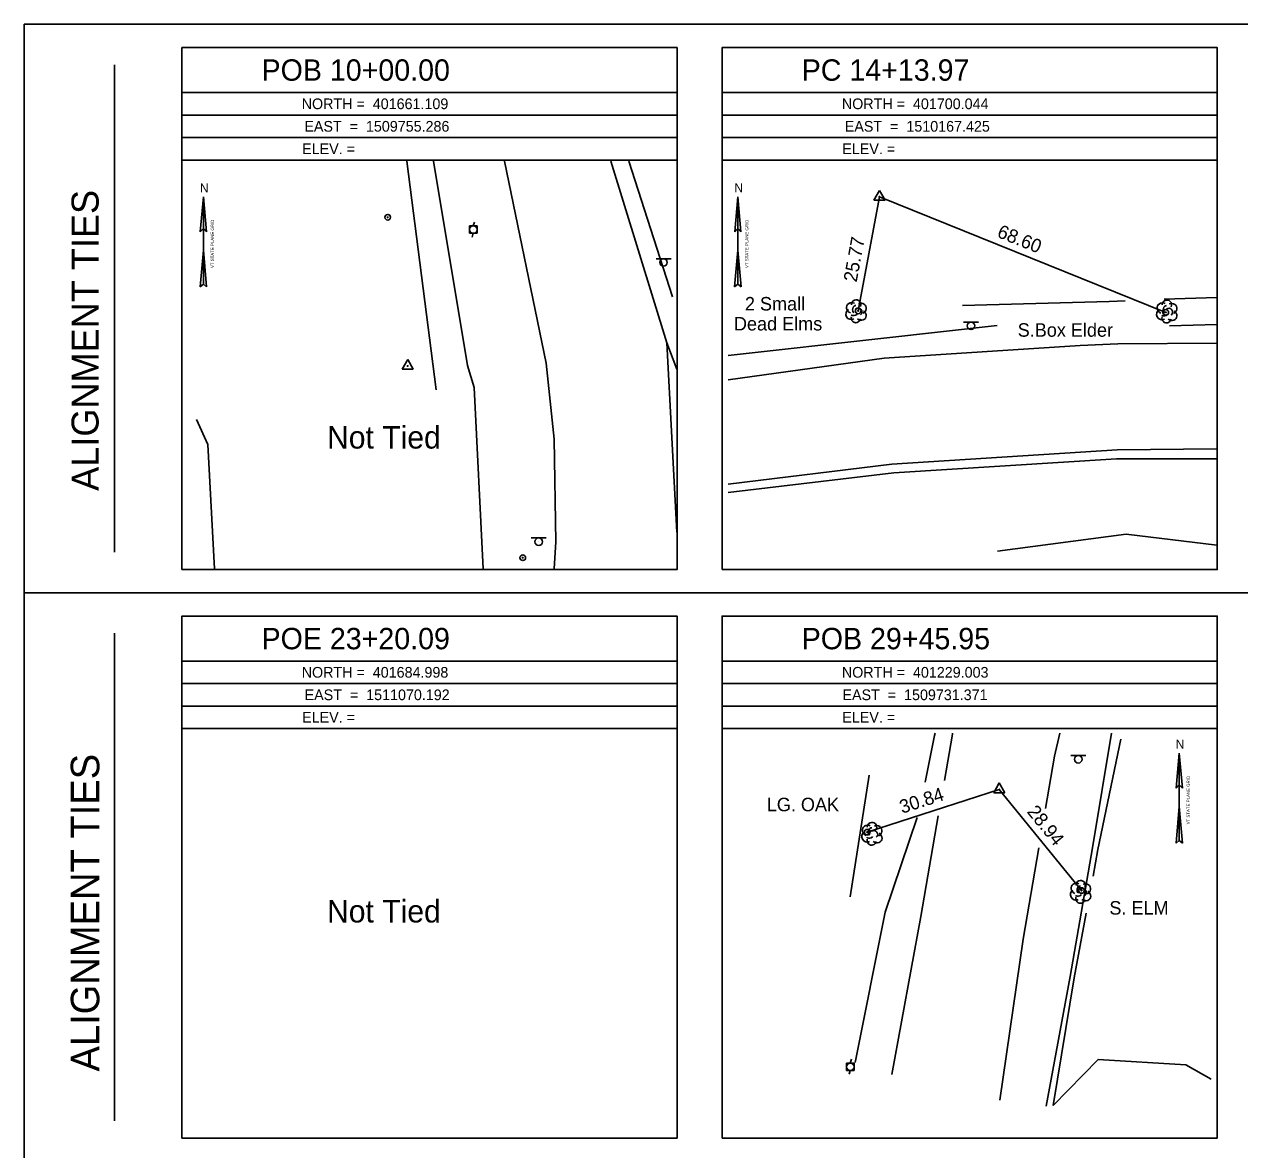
# Model space of a CAD drawing. Extents: x 1508412 to 1509054, y 401108 to 401963.
# Drawn here: x 1508411.9 to 1508681.9, y 401277.6 to 401527.7 of the extents above; entities that cross this region are included whole.
import ezdxf

# ---------------------------------------------------------------- set-up
doc = ezdxf.new("R2010")
doc.units = 0
for name, color, linetype in [('CBP', 7, 'Continuous'), ('CPH', 7, 'Continuous'), ('Default', 7, 'Continuous'), ('L_C', 7, 'Continuous'), ('LAWA', 7, 'Continuous'), ('LAWE', 7, 'Continuous'), ('Level 5', 7, 'Continuous'), ('LFNC', 7, 'Continuous'), ('LTD', 7, 'Continuous'), ('LWS', 7, 'Continuous'), ('NBL1', 7, 'Continuous'), ('NBL2', 7, 'Continuous'), ('NNA_P', 7, 'Continuous'), ('PET', 7, 'Continuous'), ('RGR', 7, 'Continuous'), ('SSGN', 7, 'Continuous'), ('UP', 7, 'Continuous'), ('UPGW', 7, 'Continuous')]:
    doc.layers.add(name, color=color, linetype=linetype)

msp = doc.modelspace()

# ---------------------------------------------------------------- linework, layer by layer
at = {"layer": 'CBP'}
for centre, radius in [((1508597.17, 401464.03), 0.625), ((1508597.17, 401464.03), 0.0833), ((1508665.49, 401463.7), 0.625), ((1508665.49, 401463.7), 0.0833), ((1508599.16, 401348.2), 0.625), ((1508599.16, 401348.2), 0.0833), ((1508646.76, 401335.23), 0.625), ((1508646.76, 401335.23), 0.0833)]:
    msp.add_circle(centre, radius, dxfattribs=at)
at = {"layer": 'CPH'}
for p, q in [((1508600.62, 401488.65), (1508601.87, 401490.82)), ((1508603.12, 401488.65), (1508601.87, 401490.82)), ((1508600.62, 401488.65), (1508603.12, 401488.65)), ((1508601.87, 401489.37), (1508601.87, 401489.37)), ((1508495.83, 401451.08), (1508497.08, 401453.24)), ((1508498.33, 401451.08), (1508497.08, 401453.24)), ((1508497.08, 401451.8), (1508497.08, 401451.8)), ((1508495.83, 401451.08), (1508498.33, 401451.08)), ((1508627.26, 401356.97), (1508628.51, 401359.13)), ((1508629.76, 401356.97), (1508628.51, 401359.13)), ((1508628.51, 401357.69), (1508628.51, 401357.69)), ((1508627.26, 401356.97), (1508629.76, 401356.97))]:
    msp.add_line(p, q, dxfattribs=at)
for centre in [(1508601.87, 401489.37), (1508497.08, 401451.8), (1508628.51, 401357.69)]:
    msp.add_circle(centre, 0.0833, dxfattribs=at)
at = {"layer": 'Default'}
for p, q in [((1508597.17, 401464.03), (1508601.87, 401489.37)), ((1508601.87, 401489.37), (1508665.49, 401463.7)), ((1508599.16, 401348.2), (1508628.51, 401357.69)), ((1508628.51, 401357.69), (1508646.76, 401335.23))]:
    msp.add_line(p, q, dxfattribs=at)
at = {"layer": 'LAWA'}
for points in [[(1508496.9, 401497.27), (1508503.43, 401446.52)], [(1508454.15, 401406.72), (1508452.66, 401434.32), (1508450.15, 401439.87)], [(1508612.05, 401359.27), (1508614.08, 401369.67), (1508614.23, 401370.23)], [(1508649.32, 401338.41), (1508650.42, 401344.34), (1508655.52, 401368.88)], [(1508596.45, 401297), (1508603.17, 401330.41), (1508610.27, 401351.45)], [(1508640.44, 401287.44), (1508645.11, 401315.79), (1508647.79, 401330.17)], [(1508640.44, 401287.44), (1508650.43, 401297.69), (1508669.92, 401296.5), (1508675.55, 401293.29)]]:
    msp.add_lwpolyline(points, dxfattribs=at)
at = {"layer": 'LAWE'}
msp.add_lwpolyline([(1508628.14, 401410.67), (1508656.72, 401414.43), (1508676.83, 401411.94)], dxfattribs=at)
at = {"layer": 'LFNC'}
for points in [[(1508666.32, 401460.73), (1508676.83, 401460.99)], [(1508638.88, 401287.32), (1508644.23, 401316.1), (1508649.21, 401344.75), (1508653.46, 401370.23)], [(1508595.35, 401333.79), (1508599.56, 401360.88)]]:
    msp.add_lwpolyline(points, dxfattribs=at)
at = {"layer": 'LTD'}
for p, q in [((1508596.66, 401464), (1508596.66, 401464)), ((1508596.66, 401464), (1508596.66, 401464)), ((1508665.67, 401463.95), (1508665.67, 401463.95)), ((1508665.67, 401463.95), (1508665.67, 401463.95)), ((1508600.17, 401347.89), (1508600.17, 401347.89)), ((1508600.17, 401347.89), (1508600.17, 401347.89)), ((1508646.53, 401334.99), (1508646.53, 401334.99)), ((1508646.53, 401334.99), (1508646.53, 401334.99))]:
    msp.add_line(p, q, dxfattribs=at)
for centre in [(1508596.71, 401465.43), (1508665.72, 401465.39), (1508600.22, 401349.32), (1508646.57, 401336.42)]:
    msp.add_arc(centre, 1.05, 335.5272, 180.9563, dxfattribs=at)
for centre, major_axis, ratio, start_param, end_param in [((1508595.87, 401464.66), (1.21, -0.51), 0.895232, 1.570796, 4.712389), ((1508596.46, 401464.46), (-0.208, -0.792), 0.645439, 3.141593, 6.283185), ((1508597.71, 401464.58), (-1.14, -0.48), 0.949671, 1.570796, 4.712389), ((1508664.88, 401464.62), (1.21, -0.51), 0.895232, 1.570796, 4.712389), ((1508665.46, 401464.41), (-0.208, -0.792), 0.645439, 3.141593, 6.283185), ((1508666.71, 401464.53), (-1.14, -0.48), 0.949671, 1.570796, 4.712389), ((1508595.58, 401463.29), (0.58, -1.04), 0.959034, 3.141593, 6.283185), ((1508596.66, 401462.5), (0.26, 1.06), 0.942809, 1.570796, 4.712389), ((1508596.21, 401463.25), (-0.625, -0.083), 0.423636, 0, 3.141593), ((1508597.16, 401463.83), (-0.5, 0.667), 0.989748, 3.141593, 6.283185), ((1508597.66, 401463.16), (-1.09, 0.79), 0.841452, 1.570796, 4.712389), ((1508664.59, 401463.24), (0.58, -1.04), 0.959034, 3.141593, 6.283185), ((1508665.67, 401462.45), (0.26, 1.06), 0.942809, 1.570796, 4.712389), ((1508665.21, 401463.2), (-0.625, -0.083), 0.423636, 0, 3.141593), ((1508666.17, 401463.78), (-0.5, 0.667), 0.989748, 3.141593, 6.283185), ((1508666.67, 401463.12), (-1.09, 0.79), 0.841452, 1.570796, 4.712389), ((1508599.38, 401348.55), (1.21, -0.51), 0.895232, 1.570796, 4.712389), ((1508599.96, 401348.35), (-0.208, -0.792), 0.645439, 3.141593, 6.283185), ((1508601.21, 401348.47), (-1.14, -0.48), 0.949671, 1.570796, 4.712389), ((1508599.09, 401347.18), (0.58, -1.04), 0.959034, 3.141593, 6.283185), ((1508600.17, 401346.39), (0.26, 1.06), 0.942809, 1.570796, 4.712389), ((1508599.71, 401347.14), (-0.625, -0.083), 0.423636, 0, 3.141593), ((1508600.67, 401347.72), (-0.5, 0.667), 0.989748, 3.141593, 6.283185), ((1508601.17, 401347.05), (-1.09, 0.79), 0.841452, 1.570796, 4.712389), ((1508645.74, 401335.66), (1.21, -0.51), 0.895232, 1.570796, 4.712389), ((1508646.32, 401335.45), (-0.208, -0.792), 0.645439, 3.141593, 6.283185), ((1508647.03, 401334.82), (-0.5, 0.667), 0.989748, 3.141593, 6.283185), ((1508647.57, 401335.57), (-1.14, -0.48), 0.949671, 1.570796, 4.712389), ((1508645.44, 401334.28), (0.58, -1.04), 0.959034, 3.141593, 6.283185), ((1508646.53, 401333.49), (0.26, 1.06), 0.942809, 1.570796, 4.712389), ((1508646.07, 401334.24), (-0.625, -0.083), 0.423636, 0, 3.141593), ((1508647.53, 401334.16), (-1.09, 0.79), 0.841452, 1.570796, 4.712389)]:
    msp.add_ellipse(centre, major_axis=major_axis, ratio=ratio, start_param=start_param, end_param=end_param, dxfattribs=at)
at = {"layer": 'LWS'}
for points in [[(1508502.79, 401497.27), (1508510.35, 401451.87), (1508511.84, 401447.03), (1508513.86, 401406.72)], [(1508656.44, 401466.27), (1508652.94, 401466.09), (1508620.31, 401465.21)], [(1508676.83, 401466.98), (1508665.13, 401466.61)]]:
    msp.add_lwpolyline(points, dxfattribs=at)
at = {"layer": 'NBL1'}
msp.add_lwpolyline([(1508411.91, 401107.72), (1509051.91, 401107.72), (1509051.91, 401527.72), (1508411.91, 401527.72)], close=True, dxfattribs=at)
at = {"layer": 'NBL2'}
for p, q in [((1508431.91, 401410.38), (1508431.91, 401518.72)), ((1508556.91, 401512.55), (1508446.91, 401512.55)), ((1508676.91, 401512.55), (1508566.91, 401512.55)), ((1508556.91, 401507.55), (1508446.91, 401507.55)), ((1508676.91, 401507.55), (1508566.91, 401507.55)), ((1508556.91, 401502.55), (1508446.91, 401502.55)), ((1508676.91, 401502.55), (1508566.91, 401502.55)), ((1508556.91, 401497.55), (1508446.91, 401497.55)), ((1508676.91, 401497.55), (1508566.91, 401497.55)), ((1508411.91, 401401.38), (1509051.91, 401401.38)), ((1508431.91, 401284.05), (1508431.91, 401392.38)), ((1508556.91, 401386.22), (1508446.91, 401386.22)), ((1508676.91, 401386.22), (1508566.91, 401386.22)), ((1508556.91, 401381.22), (1508446.91, 401381.22)), ((1508676.91, 401381.22), (1508566.91, 401381.22)), ((1508556.91, 401376.22), (1508446.91, 401376.22)), ((1508676.91, 401376.22), (1508566.91, 401376.22)), ((1508556.91, 401371.22), (1508446.91, 401371.22)), ((1508676.91, 401371.22), (1508566.91, 401371.22))]:
    msp.add_line(p, q, dxfattribs=at)
for points in [[(1508446.91, 401406.55), (1508556.91, 401406.55), (1508556.91, 401522.55), (1508446.91, 401522.55)], [(1508566.91, 401406.55), (1508676.91, 401406.55), (1508676.91, 401522.55), (1508566.91, 401522.55)], [(1508446.91, 401280.22), (1508556.91, 401280.22), (1508556.91, 401396.22), (1508446.91, 401396.22)], [(1508566.91, 401280.22), (1508676.91, 401280.22), (1508676.91, 401396.22), (1508566.91, 401396.22)]]:
    msp.add_lwpolyline(points, close=True, dxfattribs=at)
at = {"layer": 'NNA_P'}
for p, q in [((1508450.99, 401481.58), (1508451.69, 401489.37)), ((1508451.69, 401469.99), (1508451.69, 401489.37)), ((1508452.38, 401481.58), (1508451.69, 401489.37)), ((1508569.73, 401481.58), (1508570.43, 401489.37)), ((1508570.43, 401469.99), (1508570.43, 401489.37)), ((1508571.12, 401481.58), (1508570.43, 401489.37)), ((1508450.99, 401481.58), (1508451.69, 401482.34)), ((1508452.38, 401481.58), (1508451.69, 401482.34)), ((1508569.73, 401481.58), (1508570.43, 401482.34)), ((1508571.12, 401481.58), (1508570.43, 401482.34)), ((1508451.69, 401477.52), (1508450.97, 401469.35)), ((1508451.69, 401477.52), (1508452.41, 401469.35)), ((1508570.43, 401477.52), (1508569.71, 401469.35)), ((1508570.43, 401477.52), (1508571.15, 401469.35)), ((1508451.69, 401469.99), (1508450.97, 401469.35)), ((1508451.69, 401469.99), (1508452.41, 401469.35)), ((1508570.43, 401469.99), (1508569.71, 401469.35)), ((1508570.43, 401469.99), (1508571.15, 401469.35)), ((1508667.78, 401357.96), (1508668.47, 401365.75)), ((1508668.48, 401346.37), (1508668.47, 401365.75)), ((1508669.17, 401357.96), (1508668.47, 401365.75)), ((1508667.78, 401357.96), (1508668.47, 401358.72)), ((1508669.17, 401357.96), (1508668.47, 401358.72)), ((1508668.48, 401353.9), (1508667.76, 401345.73)), ((1508668.47, 401353.9), (1508669.2, 401345.73)), ((1508668.48, 401346.37), (1508667.76, 401345.73)), ((1508668.48, 401346.37), (1508669.2, 401345.73))]:
    msp.add_line(p, q, dxfattribs=at)
at = {"layer": 'PET'}
for points in [[(1508518.59, 401497.27), (1508527.84, 401452.39), (1508529.59, 401435.54), (1508529.95, 401412.68), (1508529.59, 401406.72)], [(1508542.24, 401497.27), (1508554.62, 401456.93)], [(1508554.62, 401456.93), (1508556.87, 401451.08)], [(1508554.62, 401456.93), (1508556.87, 401414.86)], [(1508568.3, 401448.68), (1508602.96, 401453.53), (1508646.5, 401456.32), (1508654.83, 401456.68), (1508676.83, 401456.87)], [(1508568.3, 401425.55), (1508604.63, 401429.98), (1508654.68, 401433.18), (1508676.83, 401433.38)], [(1508616.3, 401359.7), (1508618.07, 401369.97)], [(1508618.07, 401369.97), (1508618.11, 401370.23)], [(1508640.75, 401365.09), (1508641.98, 401370.23)], [(1508638.76, 401353.42), (1508640.75, 401365.09)], [(1508604.61, 401294.35), (1508611.1, 401329.43), (1508614.95, 401351.81)], [(1508628.61, 401288.65), (1508633.81, 401324.4), (1508637.28, 401344.74)]]:
    msp.add_lwpolyline(points, dxfattribs=at)
at = {"layer": 'RGR'}
for points in [[(1508546.17, 401497.27), (1508555.94, 401467.18)], [(1508568.3, 401454.1), (1508602.84, 401457.94), (1508628.03, 401460.8)], [(1508568.3, 401423.67), (1508605.08, 401428.06), (1508654.53, 401431.17), (1508676.83, 401431.17)]]:
    msp.add_lwpolyline(points, dxfattribs=at)
at = {"layer": 'SSGN'}
for p, q in [((1508552.26, 401475.63), (1508555.59, 401475.63)), ((1508553.9, 401474.8), (1508553.9, 401474.8)), ((1508620.56, 401461.56), (1508623.9, 401461.56)), ((1508622.21, 401460.72), (1508622.21, 401460.72)), ((1508524.53, 401413.57), (1508527.86, 401413.57)), ((1508526.18, 401412.74), (1508526.18, 401412.74)), ((1508644.4, 401365.22), (1508647.74, 401365.22)), ((1508646.05, 401364.39), (1508646.05, 401364.39))]:
    msp.add_line(p, q, dxfattribs=at)
for centre in [(1508553.9, 401474.8), (1508622.21, 401460.72), (1508526.18, 401412.74), (1508646.05, 401364.39)]:
    msp.add_circle(centre, 0.833, dxfattribs=at)
at = {"layer": 'UP'}
for p, q in [((1508510.82, 401481.27), (1508510.82, 401482.93)), ((1508510.82, 401482.93), (1508512.48, 401482.93)), ((1508511.9, 401483.77), (1508511.65, 401482.93)), ((1508511.65, 401482.1), (1508511.65, 401482.1)), ((1508512.48, 401482.93), (1508512.48, 401481.27)), ((1508512.48, 401481.27), (1508510.82, 401481.27)), ((1508511.4, 401480.43), (1508511.65, 401481.27)), ((1508595.66, 401297.72), (1508595.41, 401296.89)), ((1508594.58, 401295.22), (1508594.58, 401296.89)), ((1508594.58, 401296.89), (1508596.24, 401296.89)), ((1508596.24, 401295.22), (1508594.58, 401295.22)), ((1508595.16, 401294.39), (1508595.41, 401295.22)), ((1508595.41, 401296.05), (1508595.41, 401296.05)), ((1508596.24, 401296.89), (1508596.24, 401295.22))]:
    msp.add_line(p, q, dxfattribs=at)
for centre in [(1508511.65, 401482.1), (1508595.41, 401296.05)]:
    msp.add_circle(centre, 0.833, dxfattribs=at)
at = {"layer": 'UPGW'}
for centre, radius in [((1508492.64, 401484.83), 0.625), ((1508492.64, 401484.83), 0.0833), ((1508522.64, 401409.18), 0.625), ((1508522.64, 401409.18), 0.0833)]:
    msp.add_circle(centre, radius, dxfattribs=at)

# ---------------------------------------------------------------- texts
at = {"layer": 'Default'}
for s, rotation, p in [('68.60', 338.0266, (1508627.82, 401480.52)), ('25.77', 79.4995, (1508596.81, 401470.29)), ('30.84', 17.9163, (1508606.91, 401352.28)), ('28.94', 309.0913, (1508634.51, 401352.68))]:
    msp.add_text(s, height=3, rotation=rotation, dxfattribs=at).set_placement(p)
at = {"layer": 'L_C'}
for s, p in [('2 Small', (1508571.99, 401464.12)), ('Dead Elms', (1508569.55, 401459.68)), ('S.Box Elder', (1508632.59, 401458.29)), ('LG. OAK', (1508576.85, 401352.84)), ('S. ELM', (1508652.96, 401329.88))]:
    msp.add_text(s, height=3, dxfattribs=at).set_placement(p)
at = {"layer": 'Level 5'}
for p in [(1508479.16, 401433.44), (1508479.16, 401328.12)]:
    msp.add_text('Not Tied', height=5, dxfattribs=at).set_placement(p)
at = {"layer": 'NBL2'}
for s, height, p in [('    POB 10+00.00   ', 4.75, (1508457.55, 401515.18)), ('    PC 14+13.97    ', 4.75, (1508577.55, 401515.18)), ('NORTH =  401661.109 ', 2.375, (1508473.53, 401508.86)), ('NORTH =  401700.044 ', 2.375, (1508593.53, 401508.86)), ('EAST  =  1509755.286', 2.375, (1508474.12, 401503.86)), ('EAST  =  1510167.425', 2.375, (1508594.18, 401503.86)), ('ELEV. =             ', 2.375, (1508473.63, 401498.86)), ('ELEV. =             ', 2.375, (1508593.63, 401498.86)), ('    POE 23+20.09   ', 4.75, (1508457.55, 401388.84)), ('    POB 29+45.95   ', 4.75, (1508577.55, 401388.84)), ('NORTH =  401684.998 ', 2.375, (1508473.53, 401382.53)), ('NORTH =  401229.003 ', 2.375, (1508593.53, 401382.53)), ('EAST  =  1511070.192', 2.375, (1508474.18, 401377.53)), ('EAST  =  1509731.371', 2.375, (1508593.67, 401377.53)), ('ELEV. =             ', 2.375, (1508473.63, 401372.53)), ('ELEV. =             ', 2.375, (1508593.63, 401372.53))]:
    msp.add_text(s, height=height, dxfattribs=at).set_placement(p)
for height, p in [(6, (1508428.41, 401424.04)), (6.3332, (1508428.57, 401295.01))]:
    msp.add_text('ALIGNMENT TIES', height=height, rotation=90, dxfattribs=at).set_placement(p)
at = {"layer": 'NNA_P'}
for p in [(1508450.93, 401490.38), (1508569.67, 401490.38), (1508667.71, 401366.76)]:
    msp.add_text('N', height=1.97, dxfattribs=at).set_placement(p)
for p in [(1508454.04, 401473.56), (1508572.78, 401473.56), (1508670.83, 401349.94)]:
    msp.add_text('VT STATE PLANE GRID', height=0.7, rotation=90.0204, dxfattribs=at).set_placement(p)

doc.saveas('drawing.dxf')
